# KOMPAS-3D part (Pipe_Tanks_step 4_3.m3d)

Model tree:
1. X Axis
2. Y Axis
3. Z Axis  (labels: T-Bend Dn 150; Pipe Dn 150; Valve Dy 150)
     Òîëùèíà ñòåíêè 1 = 1

Referenced files in C:\Documents and Settings\kashirsky\Мои документы\Camtasia Studio\Pipelines3D\Tanks\: Tanks_step 4.a3d
Referenced files in C:\Program Files\ASCON\KOMPAS-3D V10\Libs\Piping\LOAD\: Piping_C_Pipe_150_1000.m3d
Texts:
  Pipe Dn 150
  Steel ASTM A295
  Three Point Plane
  Plane at Angle
  Line and Point Plane
  Axis through Two Vertices
  Axis of Feature
  Axis of Conical Surface
  Axis through Edge
  Trim by Surface
  Trim by Sketch
  Feature with No History
  Intersection Axis of Two Planes
  Two Line Plane
  Line and Face Plane
  Bend by line
  Hole in sheet body
  Cut in sheet body
  Point in CM
  Linear Dimension from Line to Point
  Surface Finish Symbol
  Geometric Tolerance Symbol
  Leader #1
  Leader #2
  Leader #3
  Shape Deviations and Datum
  Node point number
  Mark of coordination axis
  Node point designation
  Mark/Reference designation with leader
  Mark/reference designation on line
  Mark/Reference designation without leader
  T-Bend Dn 150
  Valve Dy 150
  Plane of section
